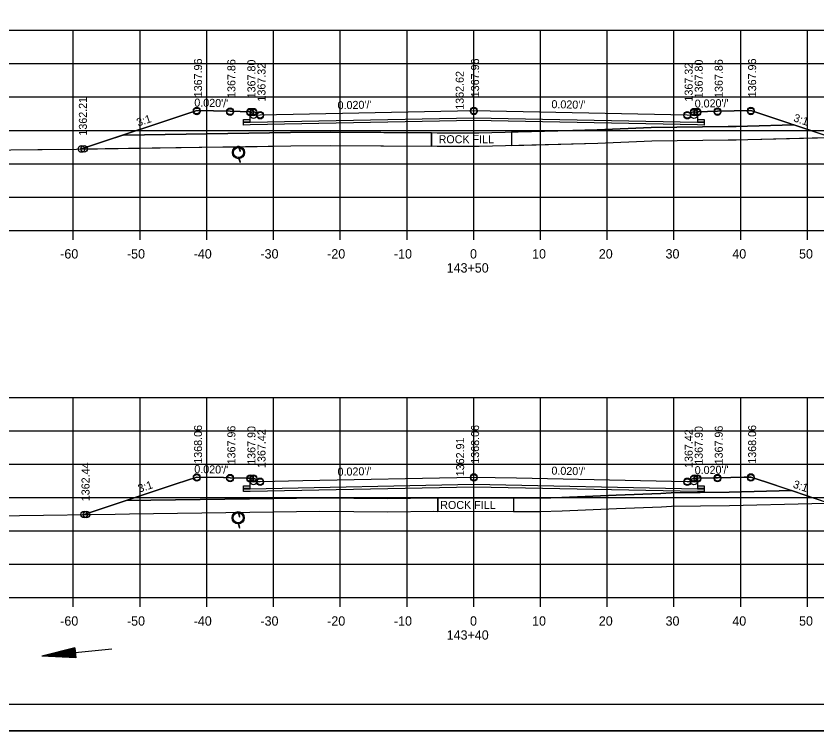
# Model space of a CAD drawing. Extents: x 1374311 to 1383814, y 384102 to 406278.
# Drawn here: x 1381560.1 to 1381679.9, y 389871.4 to 389978.5 of the extents above; entities that cross this region are included whole.
import ezdxf

# ---------------------------------------------------------------- set-up
doc = ezdxf.new("R2010")
doc.units = 0
for name, color, linetype in [('R_Axis', 7, 'Continuous'), ('R_Axis Annot', 7, 'Continuous'), ('R_Border', 7, 'Continuous'), ('R_Draft', 7, 'Continuous'), ('R_Exist Surface', 7, 'Continuous'), ('R_Fin Surface', 7, 'Continuous'), ('R_Grid', 7, 'Continuous'), ('R_No Plot', 7, 'Continuous'), ('R_Water', 7, 'Continuous'), ('R_Xsect Elev', 7, 'Continuous'), ('R_Xsect Slope', 7, 'Continuous')]:
    doc.layers.add(name, color=color, linetype=linetype)

msp = doc.modelspace()

# ---------------------------------------------------------------- linework, layer by layer
at = {"layer": 'R_Axis'}
for p, q in [((1381488.66, 389946.37), (1381768.66, 389946.37)), ((1381568.66, 389944.97), (1381568.66, 389946.37)), ((1381578.66, 389944.97), (1381578.66, 389946.37)), ((1381588.66, 389944.97), (1381588.66, 389946.37)), ((1381598.66, 389944.97), (1381598.66, 389946.37)), ((1381608.66, 389944.97), (1381608.66, 389946.37)), ((1381618.66, 389944.97), (1381618.66, 389946.37)), ((1381628.66, 389944.97), (1381628.66, 389946.37)), ((1381638.66, 389944.97), (1381638.66, 389946.37)), ((1381648.66, 389944.97), (1381648.66, 389946.37)), ((1381658.66, 389944.97), (1381658.66, 389946.37)), ((1381668.66, 389944.97), (1381668.66, 389946.37)), ((1381678.66, 389944.97), (1381678.66, 389946.37)), ((1381488.66, 389891.37), (1381768.66, 389891.37)), ((1381568.66, 389889.97), (1381568.66, 389891.37)), ((1381578.66, 389889.97), (1381578.66, 389891.37)), ((1381588.66, 389889.97), (1381588.66, 389891.37)), ((1381598.66, 389889.97), (1381598.66, 389891.37)), ((1381608.66, 389889.97), (1381608.66, 389891.37)), ((1381618.66, 389889.97), (1381618.66, 389891.37)), ((1381628.66, 389889.97), (1381628.66, 389891.37)), ((1381638.66, 389889.97), (1381638.66, 389891.37)), ((1381648.66, 389889.97), (1381648.66, 389891.37)), ((1381658.66, 389889.97), (1381658.66, 389891.37)), ((1381668.66, 389889.97), (1381668.66, 389891.37)), ((1381678.66, 389889.97), (1381678.66, 389891.37))]:
    msp.add_line(p, q, dxfattribs=at)
at = {"layer": 'R_Border'}
msp.add_line((1381786.84, 389875.37), (1381470.66, 389875.37), dxfattribs=at)
at = {"layer": 'R_Draft'}
for p, q in [((1381568.87, 389883.86), (1381563.97, 389882.62)), ((1381568.88, 389883.73), (1381564.8, 389882.7)), ((1381568.9, 389883.61), (1381565.66, 389882.79)), ((1381568.91, 389883.48), (1381566.48, 389882.87)), ((1381568.92, 389883.35), (1381567.33, 389882.95)), ((1381568.87, 389883.86), (1381569.02, 389882.37)), ((1381569.02, 389882.37), (1381563.97, 389882.62)), ((1381569.01, 389882.49), (1381564.8, 389882.7)), ((1381568.99, 389882.62), (1381565.66, 389882.79)), ((1381568.98, 389882.74), (1381566.48, 389882.87)), ((1381568.97, 389882.87), (1381567.33, 389882.95)), ((1381568.93, 389883.23), (1381568.16, 389883.03)), ((1381568.96, 389882.99), (1381568.16, 389883.03))]:
    msp.add_line(p, q, dxfattribs=at)
at = {"layer": 'R_Exist Surface'}
for p, q in [((1381593.41, 389959.04), (1381593.64, 389958.37)), ((1381593.41, 389957.21), (1381593.64, 389956.54)), ((1381593.34, 389904.26), (1381593.56, 389903.59)), ((1381593.34, 389902.43), (1381593.56, 389901.76))]:
    msp.add_line(p, q, dxfattribs=at)
for points in [[(1381488.66, 389957.18), (1381491.99, 389957.52), (1381495.7, 389957.55), (1381500.39, 389957.65), (1381519.45, 389957.89), (1381530.32, 389958.06), (1381536.41, 389958.09), (1381559.3, 389958.43), (1381563.35, 389958.49), (1381563.98, 389958.5), (1381569.16, 389958.57), (1381591.08, 389958.89), (1381601.24, 389959.03), (1381607.17, 389959.12), (1381623.18, 389958.98), (1381625.05, 389958.99), (1381629.45, 389958.99), (1381647.23, 389959.45), (1381655.32, 389959.81), (1381666.78, 389959.96), (1381668, 389959.97), (1381669.71, 389960.02), (1381685.16, 389960.38)], [(1381488.66, 389902.68), (1381493.2, 389902.73), (1381502.37, 389902.92), (1381513.22, 389903.06), (1381519.41, 389903.15), (1381531.4, 389903.22), (1381551.71, 389903.52), (1381557.32, 389903.57), (1381560.58, 389903.65), (1381574.95, 389903.88), (1381577.08, 389903.91), (1381595.09, 389904.17), (1381605.59, 389904.33), (1381615.8, 389904.23), (1381622.61, 389904.3), (1381638.57, 389904.27), (1381641.93, 389904.36), (1381650.07, 389904.72), (1381656.77, 389904.98), (1381658.31, 389905.05), (1381666.99, 389905.15), (1381679.33, 389905.49), (1381681.22, 389905.52)]]:
    msp.add_lwpolyline(points, dxfattribs=at)
for centre in [(1381593.41, 389958.04), (1381593.36, 389903.33)]:
    msp.add_circle(centre, 0.917, dxfattribs=at)
at = {"layer": 'R_Fin Surface'}
for p, q in [((1381576.17, 389960.67), (1381570.71, 389958.85)), ((1381622.35, 389960.98), (1381622.35, 389958.97)), ((1381622.35, 389958.98), (1381622.35, 389960.98)), ((1381634.34, 389961.11), (1381634.34, 389959.11)), ((1381634.34, 389961.11), (1381634.34, 389959.11)), ((1381668, 389959.97), (1381669.71, 389960.02)), ((1381570.78, 389958.6), (1381591.08, 389958.89)), ((1381591.08, 389958.89), (1381593.15, 389958.92)), ((1381634.34, 389959.11), (1381647.23, 389959.45)), ((1381647.23, 389959.45), (1381655.32, 389959.81)), ((1381655.32, 389959.81), (1381666.78, 389959.96)), ((1381666.78, 389959.96), (1381668, 389959.97)), ((1381681.82, 389905.54), (1381676.25, 389907.4)), ((1381623.27, 389906.3), (1381623.27, 389904.29)), ((1381623.27, 389904.29), (1381623.27, 389906.29)), ((1381623.27, 389906.29), (1381623.27, 389906.29)), ((1381634.62, 389906.28), (1381634.62, 389904.28)), ((1381634.62, 389906.28), (1381634.62, 389904.28)), ((1381576.58, 389905.91), (1381570.29, 389903.81)), ((1381605.59, 389904.33), (1381615.8, 389904.23)), ((1381615.8, 389904.23), (1381622.61, 389904.3)), ((1381622.61, 389904.3), (1381623.27, 389904.29)), ((1381634.62, 389904.28), (1381638.57, 389904.27))]:
    msp.add_line(p, q, dxfattribs=at)
for points in [[(1381569.9, 389958.58), (1381587.15, 389964.33), (1381592.15, 389964.23), (1381595.15, 389964.17), (1381595.65, 389964.17), (1381595.66, 389963.67), (1381596.66, 389963.69), (1381628.66, 389964.33), (1381660.66, 389963.69), (1381661.66, 389963.67), (1381661.67, 389964.17), (1381662.17, 389964.17), (1381665.17, 389964.23), (1381670.17, 389964.33), (1381682.46, 389960.23)], [(1381662.17, 389963.81), (1381662.18, 389962.66), (1381663.18, 389962.66), (1381663.17, 389962.16), (1381662.17, 389962.18), (1381628.66, 389962.85), (1381595.15, 389962.18), (1381594.15, 389962.16), (1381594.16, 389962.66), (1381595.16, 389962.66), (1381595.15, 389963.81)], [(1381576.17, 389960.67), (1381601.21, 389961.03), (1381607.17, 389961.12), (1381623.18, 389960.98), (1381625.05, 389960.99), (1381629.43, 389960.99), (1381647.15, 389961.45), (1381655.26, 389961.81), (1381666.76, 389961.96), (1381667.96, 389961.97), (1381669.66, 389962.02), (1381676.63, 389962.18)], [(1381676.63, 389962.18), (1381669.66, 389962.02), (1381667.96, 389961.97), (1381666.76, 389961.96), (1381655.26, 389961.81), (1381647.15, 389961.45), (1381634.34, 389961.11)], [(1381669.71, 389960.02), (1381682.24, 389960.31), (1381676.63, 389962.18)], [(1381622.35, 389960.98), (1381607.17, 389961.12), (1381601.21, 389961.03), (1381576.17, 389960.67)], [(1381576.17, 389960.67), (1381576.17, 389960.67)], [(1381593.65, 389958.92), (1381601.24, 389959.03), (1381607.17, 389959.12), (1381622.35, 389958.98)], [(1381570.78, 389958.6), (1381570.78, 389958.6)], [(1381570.29, 389903.81), (1381584.09, 389908.41), (1381587.15, 389909.43), (1381591.15, 389909.35), (1381592.15, 389909.33), (1381594.55, 389909.28), (1381595.15, 389909.27), (1381595.25, 389909.27), (1381595.65, 389909.27), (1381595.66, 389908.87), (1381595.66, 389908.77), (1381595.86, 389908.77), (1381596.66, 389908.79), (1381603.06, 389908.92), (1381628.66, 389909.43), (1381635.06, 389909.3), (1381660.66, 389908.79), (1381660.86, 389908.78), (1381661.66, 389908.77), (1381661.67, 389909.17), (1381661.67, 389909.27), (1381661.77, 389909.27), (1381662.17, 389909.27), (1381664.57, 389909.32), (1381665.17, 389909.33), (1381669.17, 389909.41), (1381670.17, 389909.43), (1381672.5, 389908.65), (1381682.34, 389905.37)], [(1381662.17, 389908.91), (1381662.18, 389907.76), (1381663.18, 389907.75), (1381663.17, 389907.25), (1381662.17, 389907.27), (1381628.66, 389907.94), (1381595.15, 389907.27), (1381594.15, 389907.25), (1381594.16, 389907.75), (1381595.16, 389907.76), (1381595.15, 389908.91)], [(1381576.58, 389905.91), (1381595.06, 389906.17), (1381605.58, 389906.33), (1381615.8, 389906.23), (1381622.6, 389906.3), (1381638.55, 389906.27), (1381641.86, 389906.35), (1381649.98, 389906.72), (1381656.69, 389906.98), (1381658.26, 389907.05), (1381666.95, 389907.15), (1381676.25, 389907.4)], [(1381676.25, 389907.4), (1381666.95, 389907.15), (1381658.26, 389907.05), (1381656.69, 389906.98), (1381649.98, 389906.72), (1381641.86, 389906.35), (1381638.55, 389906.27), (1381634.62, 389906.28)], [(1381623.27, 389906.29), (1381622.6, 389906.3), (1381615.8, 389906.23), (1381605.58, 389906.33), (1381595.06, 389906.17), (1381576.58, 389905.91)], [(1381638.57, 389904.27), (1381641.93, 389904.36), (1381650.07, 389904.72), (1381656.77, 389904.98), (1381658.31, 389905.05), (1381666.99, 389905.15), (1381679.33, 389905.49)], [(1381679.33, 389905.49), (1381681.22, 389905.52), (1381681.82, 389905.54)], [(1381570.29, 389903.81), (1381574.95, 389903.88), (1381577.08, 389903.91), (1381595.09, 389904.17), (1381605.59, 389904.33)]]:
    msp.add_lwpolyline(points, dxfattribs=at)
for centre, radius, start, end in [((1381570.28, 389958.6), 0.5, 0, 30.9426), ((1381593.41, 389958.04), 0.917, 74.8286, 106.8126)]:
    msp.add_arc(centre, radius, start, end, dxfattribs=at)
at = {"layer": 'R_Grid'}
for p, q in [((1381488.66, 389976.37), (1381768.66, 389976.37)), ((1381568.66, 389946.37), (1381568.66, 389976.37)), ((1381578.66, 389946.37), (1381578.66, 389976.37)), ((1381588.66, 389946.37), (1381588.66, 389976.37)), ((1381598.66, 389946.37), (1381598.66, 389976.37)), ((1381608.66, 389946.37), (1381608.66, 389976.37)), ((1381618.66, 389946.37), (1381618.66, 389976.37)), ((1381628.66, 389946.37), (1381628.66, 389976.37)), ((1381638.66, 389946.37), (1381638.66, 389976.37)), ((1381648.66, 389946.37), (1381648.66, 389976.37)), ((1381658.66, 389946.37), (1381658.66, 389976.37)), ((1381668.66, 389946.37), (1381668.66, 389976.37)), ((1381678.66, 389946.37), (1381678.66, 389976.37)), ((1381488.66, 389971.37), (1381768.66, 389971.37)), ((1381488.66, 389966.37), (1381768.66, 389966.37)), ((1381488.66, 389961.37), (1381768.66, 389961.37)), ((1381488.66, 389956.37), (1381768.66, 389956.37)), ((1381488.66, 389951.37), (1381768.66, 389951.37)), ((1381488.66, 389946.37), (1381768.66, 389946.37)), ((1381488.66, 389921.37), (1381768.66, 389921.37)), ((1381568.66, 389891.37), (1381568.66, 389921.37)), ((1381578.66, 389891.37), (1381578.66, 389921.37)), ((1381588.66, 389891.37), (1381588.66, 389921.37)), ((1381598.66, 389891.37), (1381598.66, 389921.37)), ((1381608.66, 389891.37), (1381608.66, 389921.37)), ((1381618.66, 389891.37), (1381618.66, 389921.37)), ((1381628.66, 389891.37), (1381628.66, 389921.37)), ((1381638.66, 389891.37), (1381638.66, 389921.37)), ((1381648.66, 389891.37), (1381648.66, 389921.37)), ((1381658.66, 389891.37), (1381658.66, 389921.37)), ((1381668.66, 389891.37), (1381668.66, 389921.37)), ((1381678.66, 389891.37), (1381678.66, 389921.37)), ((1381488.66, 389916.37), (1381768.66, 389916.37)), ((1381488.66, 389911.37), (1381768.66, 389911.37)), ((1381488.66, 389906.37), (1381768.66, 389906.37)), ((1381488.66, 389901.37), (1381768.66, 389901.37)), ((1381488.66, 389896.37), (1381768.66, 389896.37)), ((1381488.66, 389891.37), (1381768.66, 389891.37))]:
    msp.add_line(p, q, dxfattribs=at)
at = {"layer": 'R_No Plot'}
msp.add_line((1381458.26, 389871.39), (1381791.59, 389871.39), dxfattribs=at)
for points in [[(1381458.25, 390084.73), (1381791.59, 390084.73), (1381791.59, 389871.39), (1381458.25, 389871.39)], [(1381704.58, 390080.83), (1381704.58, 390070.95), (1381740.31, 390070.95), (1381740.31, 390068.03), (1381763.51, 390068.03), (1381763.51, 390044.82), (1381786.84, 390044.82), (1381786.84, 389875.37), (1381470.66, 389875.37), (1381470.66, 390080.83)], [(1381569.9, 389958.58), (1381591.08, 389958.89), (1381601.24, 389959.03), (1381607.17, 389959.12), (1381623.18, 389958.98), (1381625.05, 389958.99), (1381629.45, 389958.99), (1381647.23, 389959.45), (1381655.32, 389959.81), (1381666.78, 389959.96), (1381668, 389959.97), (1381669.71, 389960.02), (1381682.24, 389960.31), (1381670.17, 389964.33), (1381665.17, 389964.23), (1381662.17, 389964.17), (1381662.18, 389963.02), (1381663.18, 389963.02), (1381663.17, 389962.52), (1381662.17, 389962.54), (1381628.66, 389963.21), (1381595.15, 389962.54), (1381594.15, 389962.52), (1381594.16, 389963.02), (1381595.16, 389963.02), (1381595.15, 389964.17), (1381592.15, 389964.23), (1381587.15, 389964.33)]]:
    msp.add_lwpolyline(points, close=True, dxfattribs=at)
msp.add_lwpolyline([(1381681.82, 389905.54), (1381672.5, 389908.65), (1381670.17, 389909.43), (1381669.17, 389909.41), (1381665.17, 389909.33), (1381664.57, 389909.32), (1381662.17, 389909.27), (1381662.18, 389908.12), (1381663.18, 389908.11), (1381663.17, 389907.61), (1381662.17, 389907.63), (1381628.66, 389908.3), (1381595.15, 389907.63), (1381594.15, 389907.61), (1381594.16, 389908.11), (1381595.16, 389908.12), (1381595.15, 389909.27), (1381594.55, 389909.28), (1381592.15, 389909.33), (1381591.15, 389909.35), (1381587.15, 389909.43), (1381584.09, 389908.41), (1381570.29, 389903.81), (1381570.29, 389903.81), (1381574.95, 389903.88), (1381577.08, 389903.91), (1381595.09, 389904.17), (1381605.59, 389904.33), (1381615.8, 389904.23), (1381622.61, 389904.3), (1381638.57, 389904.27), (1381641.93, 389904.36), (1381650.07, 389904.72), (1381656.77, 389904.98), (1381658.31, 389905.05), (1381666.99, 389905.15), (1381679.33, 389905.49), (1381681.22, 389905.52)], dxfattribs=at)
for centre in [(1381587.15, 389964.33), (1381587.15, 389964.33), (1381628.66, 389964.33), (1381628.66, 389964.33), (1381670.17, 389964.33), (1381670.17, 389964.33), (1381587.15, 389964.22), (1381592.15, 389964.23), (1381592.15, 389964.23), (1381592.15, 389964.12), (1381595.15, 389964.17), (1381595.15, 389964.17), (1381595.15, 389964.06), (1381595.65, 389964.17), (1381595.65, 389964.17), (1381595.65, 389964.06), (1381595.66, 389963.67), (1381596.66, 389963.69), (1381596.66, 389963.69), (1381596.66, 389963.58), (1381628.66, 389964.22), (1381660.66, 389963.69), (1381660.66, 389963.69), (1381660.66, 389963.58), (1381661.66, 389963.67), (1381661.67, 389964.17), (1381661.67, 389964.17), (1381661.67, 389964.06), (1381662.17, 389964.17), (1381662.17, 389964.17), (1381662.17, 389964.06), (1381665.17, 389964.23), (1381665.17, 389964.23), (1381665.17, 389964.12), (1381670.17, 389964.22), (1381569.9, 389958.58), (1381569.9, 389958.58), (1381569.9, 389958.58), (1381569.9, 389958.58), (1381570.28, 389958.6), (1381570.28, 389958.6), (1381587.15, 389909.43), (1381587.15, 389909.43), (1381587.15, 389909.32), (1381592.15, 389909.33), (1381592.15, 389909.33), (1381592.15, 389909.22), (1381595.15, 389909.27), (1381595.15, 389909.27), (1381595.15, 389909.16), (1381595.65, 389909.27), (1381595.65, 389909.27), (1381595.65, 389909.16), (1381628.66, 389909.43), (1381628.66, 389909.43), (1381628.66, 389909.32), (1381661.67, 389909.27), (1381661.67, 389909.27), (1381661.67, 389909.16), (1381662.17, 389909.27), (1381662.17, 389909.27), (1381662.17, 389909.16), (1381665.17, 389909.33), (1381665.17, 389909.33), (1381665.17, 389909.22), (1381670.17, 389909.43), (1381670.17, 389909.43), (1381670.17, 389909.32), (1381595.66, 389908.77), (1381596.66, 389908.79), (1381596.66, 389908.79), (1381596.66, 389908.68), (1381660.66, 389908.79), (1381660.66, 389908.79), (1381660.66, 389908.68), (1381661.66, 389908.77), (1381570.29, 389903.81), (1381570.29, 389903.81), (1381570.29, 389903.81), (1381570.29, 389903.81), (1381570.64, 389903.82), (1381570.64, 389903.82)]:
    msp.add_circle(centre, 0.5, dxfattribs=at)
at = {"layer": 'R_Water'}
for p, q in [((1381593.41, 389958.87), (1381593.64, 389958.2)), ((1381593.41, 389957.37), (1381593.64, 389956.7)), ((1381593.34, 389904.1), (1381593.56, 389903.43)), ((1381593.34, 389902.6), (1381593.56, 389901.93)), ((1381574.42, 389883.66), (1381563.97, 389882.62))]:
    msp.add_line(p, q, dxfattribs=at)
for centre in [(1381593.41, 389958.04), (1381593.36, 389903.33)]:
    msp.add_circle(centre, 0.75, dxfattribs=at)

# ---------------------------------------------------------------- texts
at = {"layer": 'R_Axis Annot'}
for s, p in [('-60', (1381566.7, 389942.17)), ('-50', (1381576.7, 389942.17)), ('-40', (1381586.7, 389942.17)), ('-30', (1381596.7, 389942.17)), ('-20', (1381606.7, 389942.17)), ('-10', (1381616.7, 389942.17)), ('0', (1381628.1, 389942.17)), ('10', (1381637.4, 389942.17)), ('20', (1381647.4, 389942.17)), ('30', (1381657.4, 389942.17)), ('40', (1381667.4, 389942.17)), ('50', (1381677.4, 389942.17)), ('143+50', (1381624.6, 389940.07)), ('-60', (1381566.7, 389887.17)), ('-50', (1381576.7, 389887.17)), ('-40', (1381586.7, 389887.17)), ('-30', (1381596.7, 389887.17)), ('-20', (1381606.7, 389887.17)), ('-10', (1381616.7, 389887.17)), ('0', (1381628.1, 389887.17)), ('10', (1381637.4, 389887.17)), ('20', (1381647.4, 389887.17)), ('30', (1381657.4, 389887.17)), ('40', (1381667.4, 389887.17)), ('50', (1381677.4, 389887.17)), ('143+40', (1381624.6, 389885.07))]:
    msp.add_text(s, height=1.4, dxfattribs=at).set_placement(p)
at = {"layer": 'R_Fin Surface'}
for p in [(1381623.4, 389959.44), (1381623.64, 389904.65)]:
    msp.add_text('ROCK FILL', height=1.2, dxfattribs=at).set_placement(p)
at = {"layer": 'R_Xsect Elev'}
for s, p in [('1367.96', (1381587.95, 389966.33)), ('1367.96', (1381629.46, 389966.33)), ('1367.96', (1381670.97, 389966.33)), ('1367.86', (1381592.95, 389966.23)), ('1367.80', (1381595.95, 389966.17)), ('1367.32', (1381597.46, 389965.69)), ('1367.32', (1381661.46, 389965.69)), ('1367.80', (1381662.97, 389966.17)), ('1367.86', (1381665.97, 389966.23)), ('1362.62', (1381627.16, 389964.46)), ('1362.21', (1381570.7, 389960.58)), ('1368.06', (1381587.95, 389911.43)), ('1367.96', (1381592.95, 389911.33)), ('1367.90', (1381595.95, 389911.27)), ('1368.06', (1381629.46, 389911.43)), ('1367.90', (1381662.97, 389911.27)), ('1367.96', (1381665.97, 389911.33)), ('1368.06', (1381670.97, 389911.43)), ('1367.42', (1381597.46, 389910.79)), ('1367.42', (1381661.46, 389910.79)), ('1362.91', (1381627.22, 389909.55)), ('1362.44', (1381571.09, 389905.81))]:
    msp.add_text(s, height=1.2, rotation=90, dxfattribs=at).set_placement(p)
at = {"layer": 'R_Xsect Slope'}
for s, rotation, p in [("0.020'/'", 358.8542, (1381586.78, 389964.94)), ("0.020'/'", 1.1458, (1381661.78, 389964.77)), ("0.020'/'", 1.1458, (1381608.27, 389964.53)), ("0.020'/'", 358.8542, (1381640.29, 389964.7)), ('3:1', 18.4349, (1381578.36, 389961.93)), ('3:1', 341.5651, (1381676.47, 389962.76)), ("0.020'/'", 358.8542, (1381586.78, 389910.04)), ("0.020'/'", 1.1458, (1381608.27, 389909.62)), ("0.020'/'", 358.8542, (1381640.29, 389909.8)), ("0.020'/'", 1.1458, (1381661.78, 389909.86)), ('3:1', 18.4349, (1381578.56, 389907.09)), ('3:1', 341.5651, (1381676.41, 389907.87))]:
    msp.add_text(s, height=1.2, rotation=rotation, dxfattribs=at).set_placement(p)

doc.saveas('drawing.dxf')
